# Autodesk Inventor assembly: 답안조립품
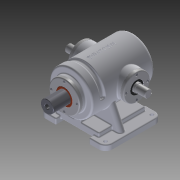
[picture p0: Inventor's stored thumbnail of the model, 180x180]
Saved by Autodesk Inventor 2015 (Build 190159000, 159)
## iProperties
Created: 2015-10
Part Number: 답안조립품
Document SubType Name: Assembly
Designer: youjin03
Mass: 9437.34 g
Surface Area: 4327.34 cm^2
Volume: 2315.26 cm^3
Density: 4.07615 g/cm^3
Author: youjin03
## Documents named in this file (13)
- C:\Users\youjin03\Desktop\351019V1006\답안조립품.iam
- C:\Users\youjin03\Desktop\351019V1006\본체.ipt
- C:\Users\youjin03\Desktop\351019V1006\슬라이드 커버.ipt
- C:\Users\youjin03\Desktop\351019V1006\M4x0.7.ipt
- C:\Users\youjin03\Desktop\351019V1006\축 커버.ipt
- C:\Users\youjin03\Desktop\351019V1006\오일실.ipt
- 오일실.ipt
- C:\Users\youjin03\Desktop\351019V1006\베어링 6205.ipt
- 베어링 6205.ipt
- C:\Users\youjin03\Desktop\351019V1006\편심축.ipt
- C:\Users\youjin03\Desktop\351019V1006\부시.ipt
- C:\Users\youjin03\Desktop\351019V1006\가변스프링.ipt
- C:\Users\youjin03\Desktop\351019V1006\슬라이드.ipt
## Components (13 placed, 2 different names)
1. 가변스프링:1 — Mate:23, Mate:24, Mate:25, Mate:26
2. M4x0.7:1 — Insert:1
3. M4x0.7:2
4. M4x0.7:3
5. M4x0.7:4
6. M4x0.7:5 — Insert:2
7. M4x0.7:6
8. M4x0.7:7
9. M4x0.7:8
10. M4x0.7:9 — Insert:3
11. M4x0.7:10
12. M4x0.7:11
13. M4x0.7:12
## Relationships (7: Mate 4, Insert 3)
- Insert:1: M4x0.7:1
- Insert:2: M4x0.7:5
- Insert:3: M4x0.7:9
- Mate:23: 가변스프링:1
- Mate:24: 가변스프링:1
- Mate:25: 가변스프링:1
- Mate:26: 가변스프링:1
